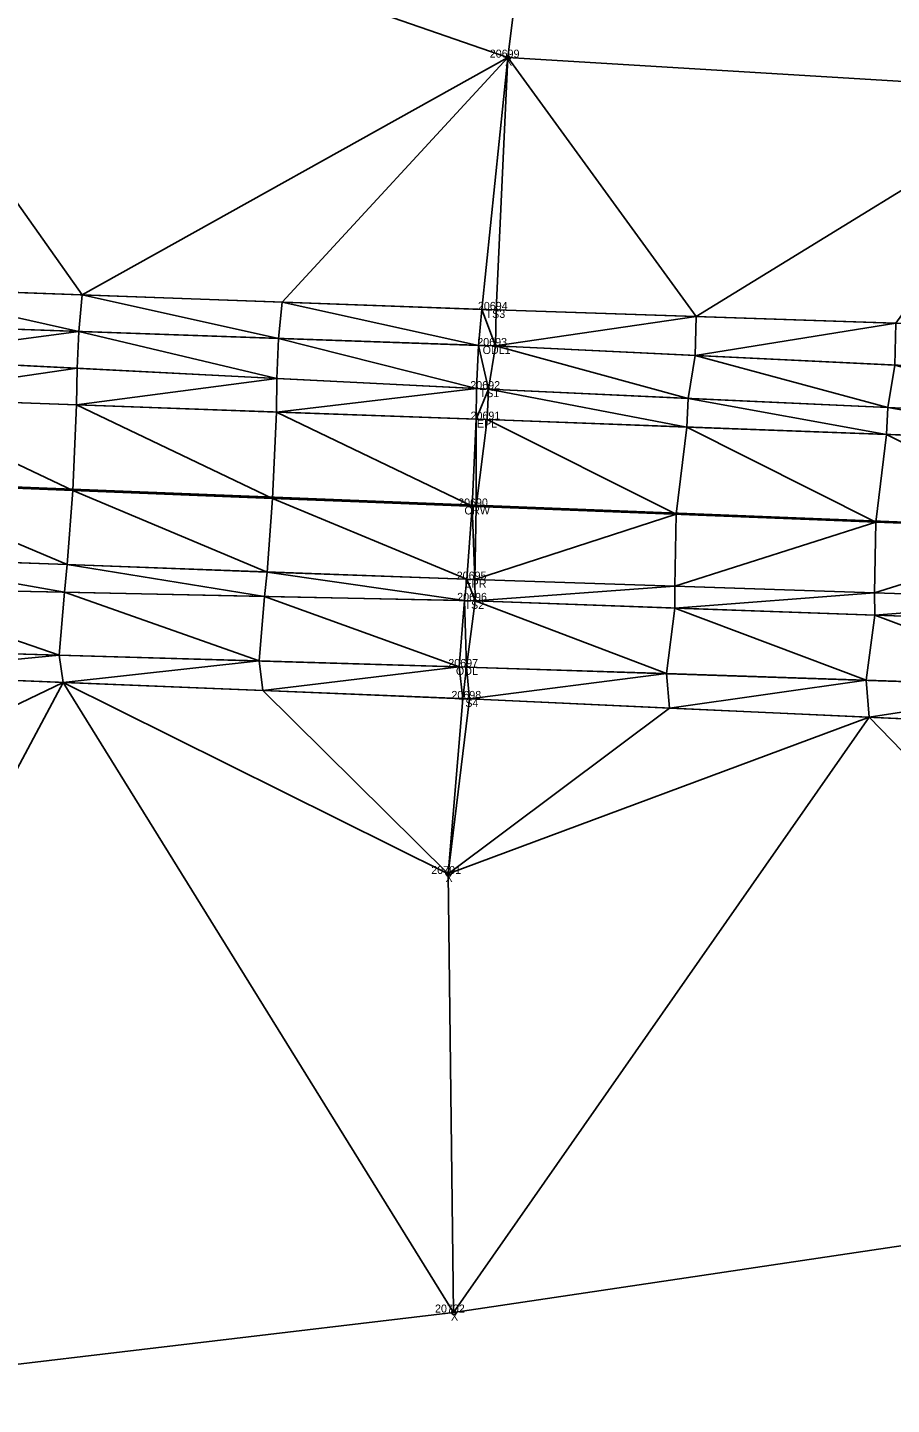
# Model space of a CAD drawing. Extents: x 1966740 to 1969291, y 1117379 to 1118460.
# Drawn here: x 1968725.8 to 1968833.8, y 1117792.3 to 1117964.4 of the extents above; entities that cross this region are included whole.
import ezdxf

# ---------------------------------------------------------------- set-up
doc = ezdxf.new("R2010")
doc.units = 0
for name, color, linetype in [('Level 1', 7, 'Continuous'), ('Level 3', 7, 'Continuous'), ('Level 30', 7, 'Continuous'), ('Level 35', 7, 'Continuous'), ('Level 50', 7, 'Continuous'), ('Level 52', 7, 'Continuous'), ('Level 53', 7, 'Continuous'), ('Level 56', 7, 'Continuous'), ('Level 6', 7, 'Continuous'), ('Level 62', 7, 'Continuous')]:
    doc.layers.add(name, color=color, linetype=linetype)

msp = doc.modelspace()

# ---------------------------------------------------------------- linework, layer by layer
at = {"layer": 'Level 1'}
msp.add_line((1968120.33, 1117930.94), (1969279.02, 1117884.95), dxfattribs=at)
at = {"layer": 'Level 3'}
for points in [[(1968532.27, 1117940.77), (1968682.68, 1117932.75), (1968784.38, 1117929.07), (1968872.44, 1117926.13)], [(1968531.49, 1117931.42), (1968682.06, 1117924.3), (1968783.42, 1117919.17), (1968888.7, 1117914.33), (1968991.06, 1117912.02), (1969093.07, 1117907.16), (1969191.83, 1117902.92), (1969283.72, 1117899.63)], [(1968530.54, 1117925.7), (1968681.97, 1117919.01), (1968783.23, 1117915.36), (1968888.64, 1117911.44), (1968991.22, 1117907.09), (1969091.98, 1117903.06), (1969191.09, 1117898.66), (1969283.27, 1117895.43)], [(1968529.36, 1117916.3), (1968681.48, 1117908.5), (1968781.89, 1117904.51), (1968887.49, 1117900.39), (1968989.06, 1117896.4), (1969090.87, 1117891.24), (1969190.23, 1117887.94), (1969284.4, 1117884.73)], [(1968527.82, 1117906.41), (1968680.79, 1117899.07), (1968781.71, 1117895.37), (1968887.86, 1117891.84), (1968988.65, 1117888.23), (1969090.1, 1117882.83), (1969189.3, 1117879.04), (1969282.94, 1117875.42)], [(1968528.99, 1117899.6), (1968680.45, 1117894.84), (1968781.74, 1117892.71), (1968887.7, 1117888.94), (1968987.81, 1117885.08), (1969089.75, 1117880.01), (1969189.02, 1117876.39), (1969282.76, 1117873.05)], [(1968528.68, 1117880.51), (1968680.3, 1117884.55), (1968781.05, 1117880.46), (1968887.57, 1117875.57), (1968986, 1117872.85), (1969087.95, 1117867.56), (1969189.32, 1117864.4), (1969289.73, 1117862.33)]]:
    msp.add_lwpolyline(points, dxfattribs=at)
at = {"layer": 'Level 30'}
for centre in [(1968785.82, 1117960.59), (1968778.37, 1117858.59), (1968779.05, 1117803.79)]:
    msp.add_circle(centre, 0.25, dxfattribs=at)
at = {"layer": 'Level 35'}
for points in [[(1968687.63, 1117994.6), (1968789.99, 1117994), (1968785.82, 1117960.59)], [(1968687.63, 1117994.6), (1968785.82, 1117960.59), (1968732.64, 1117930.94)], [(1968687.63, 1117994.6), (1968732.64, 1117930.94), (1968707.66, 1117931.85)], [(1968785.82, 1117960.59), (1968789.99, 1117994), (1968855.24, 1117956.42)], [(1968732.64, 1117930.94), (1968785.82, 1117960.59), (1968757.62, 1117930.04)], [(1968757.62, 1117930.04), (1968785.82, 1117960.59), (1968782.6, 1117929.13)], [(1968782.6, 1117929.13), (1968785.82, 1117960.59), (1968784.38, 1117929.07)], [(1968784.38, 1117929.07), (1968785.82, 1117960.59), (1968809.36, 1117928.24)], [(1968785.82, 1117960.59), (1968855.24, 1117956.42), (1968809.36, 1117928.24)], [(1968809.36, 1117928.24), (1968855.24, 1117956.42), (1968834.35, 1117927.4)], [(1968707.21, 1117927.24), (1968707.66, 1117931.85), (1968732.19, 1117926.37)], [(1968707.66, 1117931.85), (1968732.64, 1117930.94), (1968732.19, 1117926.37)], [(1968732.19, 1117926.37), (1968732.64, 1117930.94), (1968757.17, 1117925.5)], [(1968732.64, 1117930.94), (1968757.62, 1117930.04), (1968757.17, 1117925.5)], [(1968757.17, 1117925.5), (1968757.62, 1117930.04), (1968782.16, 1117924.64)], [(1968757.62, 1117930.04), (1968782.6, 1117929.13), (1968782.16, 1117924.64)], [(1968782.16, 1117924.64), (1968782.6, 1117929.13), (1968784.28, 1117924.56)], [(1968782.6, 1117929.13), (1968784.38, 1117929.07), (1968784.28, 1117924.56)], [(1968784.28, 1117924.56), (1968784.38, 1117929.07), (1968809.36, 1117928.24)], [(1968784.28, 1117924.56), (1968809.36, 1117928.24), (1968809.25, 1117923.37)], [(1968809.25, 1117923.37), (1968809.36, 1117928.24), (1968834.35, 1117927.4)], [(1968707.03, 1117923.04), (1968707.21, 1117927.24), (1968732.19, 1117926.37)], [(1968809.25, 1117923.37), (1968834.35, 1117927.4), (1968834.22, 1117922.17)], [(1968707.03, 1117923.04), (1968732.19, 1117926.37), (1968731.99, 1117921.77)], [(1968731.99, 1117921.77), (1968732.19, 1117926.37), (1968756.96, 1117920.51)], [(1968732.19, 1117926.37), (1968757.17, 1117925.5), (1968756.96, 1117920.51)], [(1968756.96, 1117920.51), (1968757.17, 1117925.5), (1968781.92, 1117919.25)], [(1968757.17, 1117925.5), (1968782.16, 1117924.64), (1968781.92, 1117919.25)], [(1968706.95, 1117918.11), (1968707.03, 1117923.04), (1968731.99, 1117921.77)], [(1968781.92, 1117919.25), (1968782.16, 1117924.64), (1968783.42, 1117919.17)], [(1968782.16, 1117924.64), (1968784.28, 1117924.56), (1968783.42, 1117919.17)], [(1968783.42, 1117919.17), (1968784.28, 1117924.56), (1968808.38, 1117918.02)], [(1968784.28, 1117924.56), (1968809.25, 1117923.37), (1968808.38, 1117918.02)], [(1968808.38, 1117918.02), (1968809.25, 1117923.37), (1968833.35, 1117916.87)], [(1968809.25, 1117923.37), (1968834.22, 1117922.17), (1968833.35, 1117916.87)], [(1968706.95, 1117918.11), (1968731.99, 1117921.77), (1968731.93, 1117917.21)], [(1968731.93, 1117917.21), (1968731.99, 1117921.77), (1968756.96, 1117920.51)], [(1968833.35, 1117916.87), (1968834.22, 1117922.17), (1968858.32, 1117915.73)], [(1968731.93, 1117917.21), (1968756.96, 1117920.51), (1968756.91, 1117916.31)], [(1968756.91, 1117916.31), (1968756.96, 1117920.51), (1968781.92, 1117919.25)], [(1968706.46, 1117907.51), (1968706.95, 1117918.11), (1968731.44, 1117906.51)], [(1968706.95, 1117918.11), (1968731.93, 1117917.21), (1968731.44, 1117906.51)], [(1968756.91, 1117916.31), (1968781.92, 1117919.25), (1968781.89, 1117915.41)], [(1968781.89, 1117915.41), (1968781.92, 1117919.25), (1968783.42, 1117919.17)], [(1968781.89, 1117915.41), (1968783.42, 1117919.17), (1968783.23, 1117915.36)], [(1968783.23, 1117915.36), (1968783.42, 1117919.17), (1968808.21, 1117914.43)], [(1968783.42, 1117919.17), (1968808.38, 1117918.02), (1968808.21, 1117914.43)], [(1968808.21, 1117914.43), (1968808.38, 1117918.02), (1968833.18, 1117913.5)], [(1968808.38, 1117918.02), (1968833.35, 1117916.87), (1968833.18, 1117913.5)], [(1968731.44, 1117906.51), (1968731.93, 1117917.21), (1968756.41, 1117905.52)], [(1968731.93, 1117917.21), (1968756.91, 1117916.31), (1968756.41, 1117905.52)], [(1968756.41, 1117905.52), (1968756.91, 1117916.31), (1968781.39, 1117904.53)], [(1968756.91, 1117916.31), (1968781.89, 1117915.41), (1968781.39, 1117904.53)], [(1968833.18, 1117913.5), (1968833.35, 1117916.87), (1968858.16, 1117912.57)], [(1968833.35, 1117916.87), (1968858.32, 1117915.73), (1968858.16, 1117912.57)], [(1968781.39, 1117904.53), (1968781.89, 1117915.41), (1968781.89, 1117904.51)], [(1968781.89, 1117904.51), (1968781.89, 1117915.41), (1968783.23, 1117915.36)], [(1968781.89, 1117904.51), (1968783.23, 1117915.36), (1968806.86, 1117903.53)], [(1968783.23, 1117915.36), (1968808.21, 1117914.43), (1968806.86, 1117903.53)], [(1968806.86, 1117903.53), (1968808.21, 1117914.43), (1968831.84, 1117902.56)], [(1968808.21, 1117914.43), (1968833.18, 1117913.5), (1968831.84, 1117902.56)], [(1968831.84, 1117902.56), (1968833.18, 1117913.5), (1968856.81, 1117901.58)], [(1968833.18, 1117913.5), (1968858.16, 1117912.57), (1968856.81, 1117901.58)], [(1968705.78, 1117898.15), (1968706.46, 1117907.51), (1968730.76, 1117897.24)], [(1968706.46, 1117907.51), (1968731.44, 1117906.51), (1968730.76, 1117897.24)], [(1968730.76, 1117897.24), (1968731.44, 1117906.51), (1968755.74, 1117896.32)], [(1968731.44, 1117906.51), (1968756.41, 1117905.52), (1968755.74, 1117896.32)], [(1968755.74, 1117896.32), (1968756.41, 1117905.52), (1968780.72, 1117895.41)], [(1968756.41, 1117905.52), (1968781.39, 1117904.53), (1968780.72, 1117895.41)], [(1968780.72, 1117895.41), (1968781.39, 1117904.53), (1968781.71, 1117895.37)], [(1968781.39, 1117904.53), (1968781.89, 1117904.51), (1968781.71, 1117895.37)], [(1968781.71, 1117895.37), (1968781.89, 1117904.51), (1968806.86, 1117903.53)], [(1968781.71, 1117895.37), (1968806.86, 1117903.53), (1968806.69, 1117894.54)], [(1968806.69, 1117894.54), (1968806.86, 1117903.53), (1968831.84, 1117902.56)], [(1968806.69, 1117894.54), (1968831.84, 1117902.56), (1968831.67, 1117893.71)], [(1968831.67, 1117893.71), (1968831.84, 1117902.56), (1968856.81, 1117901.58)], [(1968831.67, 1117893.71), (1968856.81, 1117901.58), (1968856.65, 1117892.88)], [(1968705.44, 1117894.32), (1968705.78, 1117898.15), (1968730.43, 1117893.79)], [(1968705.78, 1117898.15), (1968730.76, 1117897.24), (1968730.43, 1117893.79)], [(1968730.43, 1117893.79), (1968730.76, 1117897.24), (1968755.42, 1117893.27)], [(1968730.76, 1117897.24), (1968755.74, 1117896.32), (1968755.42, 1117893.27)], [(1968755.42, 1117893.27), (1968755.74, 1117896.32), (1968780.41, 1117892.74)], [(1968755.74, 1117896.32), (1968780.72, 1117895.41), (1968780.41, 1117892.74)], [(1968704.77, 1117886.66), (1968705.44, 1117894.32), (1968729.76, 1117885.93)], [(1968705.44, 1117894.32), (1968730.43, 1117893.79), (1968729.76, 1117885.93)], [(1968729.76, 1117885.93), (1968730.43, 1117893.79), (1968754.74, 1117885.2)], [(1968730.43, 1117893.79), (1968755.42, 1117893.27), (1968754.74, 1117885.2)], [(1968780.41, 1117892.74), (1968780.72, 1117895.41), (1968781.74, 1117892.71)], [(1968780.72, 1117895.41), (1968781.71, 1117895.37), (1968781.74, 1117892.71)], [(1968781.71, 1117895.37), (1968806.69, 1117894.54), (1968781.74, 1117892.71)], [(1968781.74, 1117892.71), (1968806.69, 1117894.54), (1968806.72, 1117891.82)], [(1968806.69, 1117894.54), (1968831.67, 1117893.71), (1968806.72, 1117891.82)], [(1968754.74, 1117885.2), (1968755.42, 1117893.27), (1968779.73, 1117884.47)], [(1968755.42, 1117893.27), (1968780.41, 1117892.74), (1968779.73, 1117884.47)], [(1968779.73, 1117884.47), (1968780.41, 1117892.74), (1968780.67, 1117884.45)], [(1968780.41, 1117892.74), (1968781.74, 1117892.71), (1968780.67, 1117884.45)], [(1968780.67, 1117884.45), (1968781.74, 1117892.71), (1968805.65, 1117883.62)], [(1968781.74, 1117892.71), (1968806.72, 1117891.82), (1968805.65, 1117883.62)], [(1968806.72, 1117891.82), (1968831.67, 1117893.71), (1968831.7, 1117890.93)], [(1968831.67, 1117893.71), (1968856.65, 1117892.88), (1968831.7, 1117890.93)], [(1968831.7, 1117890.93), (1968856.65, 1117892.88), (1968856.68, 1117890.04)], [(1968805.65, 1117883.62), (1968806.72, 1117891.82), (1968830.63, 1117882.79)], [(1968806.72, 1117891.82), (1968831.7, 1117890.93), (1968830.63, 1117882.79)], [(1968830.63, 1117882.79), (1968831.7, 1117890.93), (1968855.61, 1117881.96)], [(1968831.7, 1117890.93), (1968856.68, 1117890.04), (1968855.61, 1117881.96)], [(1968704.77, 1117886.66), (1968729.76, 1117885.93), (1968705.27, 1117883.54)], [(1968705.27, 1117883.54), (1968729.76, 1117885.93), (1968730.25, 1117882.52)], [(1968729.76, 1117885.93), (1968754.74, 1117885.2), (1968730.25, 1117882.52)], [(1968730.25, 1117882.52), (1968754.74, 1117885.2), (1968755.22, 1117881.51)], [(1968754.74, 1117885.2), (1968779.73, 1117884.47), (1968755.22, 1117881.51)], [(1968677.11, 1117857.01), (1968705.27, 1117883.54), (1968730.25, 1117882.52)], [(1968755.22, 1117881.51), (1968779.73, 1117884.47), (1968780.2, 1117880.49)], [(1968779.73, 1117884.47), (1968780.67, 1117884.45), (1968780.2, 1117880.49)], [(1968780.2, 1117880.49), (1968780.67, 1117884.45), (1968781.05, 1117880.46)], [(1968780.67, 1117884.45), (1968805.65, 1117883.62), (1968781.05, 1117880.46)], [(1968781.05, 1117880.46), (1968805.65, 1117883.62), (1968806.02, 1117879.31)], [(1968805.65, 1117883.62), (1968830.63, 1117882.79), (1968806.02, 1117879.31)], [(1968677.11, 1117857.01), (1968730.25, 1117882.52), (1968682.14, 1117792.3)], [(1968682.14, 1117792.3), (1968730.25, 1117882.52), (1968779.05, 1117803.79)], [(1968730.25, 1117882.52), (1968755.22, 1117881.51), (1968778.37, 1117858.59)], [(1968730.25, 1117882.52), (1968778.37, 1117858.59), (1968779.05, 1117803.79)], [(1968806.02, 1117879.31), (1968830.63, 1117882.79), (1968830.98, 1117878.17)], [(1968830.63, 1117882.79), (1968855.61, 1117881.96), (1968830.98, 1117878.17)], [(1968830.98, 1117878.17), (1968855.61, 1117881.96), (1968855.95, 1117877.02)], [(1968755.22, 1117881.51), (1968780.2, 1117880.49), (1968778.37, 1117858.59)], [(1968778.37, 1117858.59), (1968780.2, 1117880.49), (1968781.05, 1117880.46)], [(1968778.37, 1117858.59), (1968781.05, 1117880.46), (1968806.02, 1117879.31)], [(1968778.37, 1117858.59), (1968806.02, 1117879.31), (1968830.98, 1117878.17)], [(1968778.37, 1117858.59), (1968830.98, 1117878.17), (1968779.05, 1117803.79)], [(1968779.05, 1117803.79), (1968830.98, 1117878.17), (1968887.56, 1117819.96)], [(1968830.98, 1117878.17), (1968855.95, 1117877.02), (1968887.56, 1117819.96)]]:
    msp.add_lwpolyline(points, close=True, dxfattribs=at)
at = {"layer": 'Level 50'}
for centre in [(1968784.38, 1117929.07), (1968784.28, 1117924.56), (1968783.42, 1117919.17), (1968783.23, 1117915.36), (1968781.89, 1117904.51), (1968781.71, 1117895.37), (1968781.74, 1117892.71), (1968780.67, 1117884.45), (1968781.05, 1117880.46)]:
    msp.add_circle(centre, 0.001, dxfattribs=at)
at = {"layer": 'Level 6'}
for points in [[(1968531.76, 1117937.18), (1968682.22, 1117928.11), (1968784.28, 1117924.56), (1968890.2, 1117919.49), (1968991.22, 1117915.37), (1969093.76, 1117910.9), (1969192.08, 1117906.24), (1969283.24, 1117903.06)], [(1968528.55, 1117888.35), (1968679.78, 1117887.39), (1968780.67, 1117884.45), (1968887.36, 1117880.9), (1968987.02, 1117877.31), (1969088.58, 1117870.53), (1969189.53, 1117868.6), (1969284.94, 1117865.64)]]:
    msp.add_lwpolyline(points, dxfattribs=at)

# ---------------------------------------------------------------- texts
at = {"layer": 'Level 52'}
for s, p in [('20699', (1968783.57, 1117960.59)), ('20701', (1968776.26, 1117858.59)), ('20702', (1968776.73, 1117803.79))]:
    msp.add_text(s, height=1, dxfattribs=at).set_placement(p)
at = {"layer": 'Level 53'}
for s, p in [('20694', (1968782.09, 1117929.07)), ('TS3', (1968783.05, 1117928.07)), ('20693', (1968782.01, 1117924.56)), ('ODL1', (1968782.68, 1117923.56)), ('20692', (1968781.14, 1117919.17)), ('TS1', (1968782.31, 1117918.17)), ('20691', (1968781.17, 1117915.36)), ('EPL', (1968781.97, 1117914.36)), ('20690', (1968779.62, 1117904.51)), ('CRW', (1968780.4, 1117903.51)), ('20695', (1968779.44, 1117895.37)), ('EPR', (1968780.41, 1117894.37)), ('20696', (1968779.5, 1117892.71)), ('TS2', (1968780.42, 1117891.71)), ('20698', (1968778.78, 1117880.46)), ('TS4', (1968779.7, 1117879.46))]:
    msp.add_text(s, height=1, dxfattribs=at).set_placement(p)
at = {"layer": 'Level 56'}
for s, p in [('20697', (1968778.39, 1117884.45)), ('ODL', (1968779.34, 1117883.45))]:
    msp.add_text(s, height=1, dxfattribs=at).set_placement(p)
at = {"layer": 'Level 62'}
for p in [(1968785.48, 1117959.59), (1968778.04, 1117857.59), (1968778.72, 1117802.79)]:
    msp.add_text('X', height=1, dxfattribs=at).set_placement(p)

doc.saveas('drawing.dxf')
